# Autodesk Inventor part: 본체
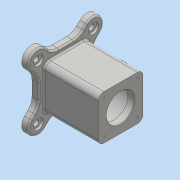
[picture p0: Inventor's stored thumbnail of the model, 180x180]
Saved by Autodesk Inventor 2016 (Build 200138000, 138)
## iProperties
Created: 2019-11
Part Number: 본체
Material: 일반
Document SubType Name: Modeling
Designer: user
Density: 1 g/cm^3
Appearance: 기본값
Author: user
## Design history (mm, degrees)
sketch "스케치1"
  geometry: L1 (-49, -49)-(49, -49); L2 (49, -49)-(49, 49); L3 (49, 49)-(-49, 49); L4 (-49, 49)-(-49, -49); L5 (-49, -49)-(49, 49); L6 (49, -49)-(-49, 49); L7 (49.497, -49.497)-(-49.497, 49.497); L8 (62.225, -36.77)-(-36.77, 62.225); L9 (-62.225, 36.77)-(36.77, -62.225); L10 (49.497, 49.497)-(-49.497, -49.497); L11 (36.77, 62.225)-(-62.225, -36.77); L12 (-36.77, -62.225)-(62.225, 36.77); A1 r 18 centre (49.497, -49.497) between (36.77, -62.225) and (62.225, -36.77); A2 r 18 centre (-49.497, 49.497) between (-36.77, 62.225) and (-62.225, 36.77); A3 r 18 centre (49.497, 49.497) between (62.225, 36.77) and (36.77, 62.225); A4 r 18 centre (-49.497, -49.497) between (-62.225, -36.77) and (-36.77, -62.225); 1 further point
  constraints: 28 end point, 8 point on circle, 8 tangent, 4 centre point, 4 midpoint, 4 parallel, 2 point on line, 1 horizontal, 1 perpendicular
  dimensions: "d72" = 98 distance of L3.end L2.end; "d73" = 98 distance of L2.end L1.end; "d74" = 18 radius of A2; "d75" = 18 radius of A4; "d76" = 140 distance of L10.start L10.end; "d77" = 140 distance of L7.start L7.end
extrude "돌출1" new body sketch "스케치1" distance "d7" = 12; taper "d8" = 0 deg
sketch "스케치2"
  geometry: L1 (-40, -40)-(40, -40); L2 (40, -40)-(40, 40); L3 (40, 40)-(-40, 40); L4 (-40, 40)-(-40, -40); L5 (-40, -40)-(40, 40); L6 (40, -40)-(-40, 40); 1 further point
  constraints: 12 end point, 2 midpoint, 2 parallel, 1 horizontal, 1 perpendicular
  dimensions: "d9" = 80 distance of L3.end L2.end; "d10" = 80 distance of L2.end L1.end
extrude "돌출2" join sketch "스케치2" distance "d11" = 98; taper "d12" = 0 deg
sketch "스케치3"
  geometry: C1 r 9 at (49.497, -49.497); A1 r 18 centre (49.497, -49.497) between (36.77, -62.225) and (62.225, -36.77) reference; 1 further point
  constraints: 1 centre point, 1 concentric
  dimensions: "d13" = 18 diameter of C1
extrude "돌출3" cut sketch "스케치3" distance "d14" = 4; taper "d15" = 0 deg
sketch "스케치4"
  geometry: C1 r 5 at (0, 0); C2 r 9 at (0, 0) reference; 1 further point
  constraints: 1 centre point, 1 concentric
  dimensions: "d16" = 10 diameter of C1
extrude "돌출4" cut sketch "스케치4" distance "d17" = 38.25; taper "d18" = 0 deg
sketch "스케치5"
  geometry: L1 (-12, 63.544)-(-12, 16.456) reference; C1 r 20 at (49, 40); 1 further point
  constraints: 1 centre point, 1 horizontal alignment, 1 midpoint
  dimensions: "d25" = 40 diameter of C1; "d78" = 61 distance from line of L1 C1.centre
extrude "돌출5" join sketch "스케치5" distance "d27" = 15; taper "d28" = 0 deg
sketch "스케치6"
  geometry: C1 r 15 at (0, 0); C2 r 20 at (0, 0) reference; 1 further point
  constraints: 1 centre point, 1 concentric
  dimensions: "d29" = 30 diameter of C1
extrude "돌출6" cut sketch "스케치6" distance "d30" = 8; taper "d31" = 0 deg
sketch "스케치7"
  geometry: C1 r 12.5 at (0, 0); C2 r 15 at (0, 0) reference; 1 further point
  constraints: 1 centre point, 1 concentric
  dimensions: "d32" = 25 diameter of C1
extrude "돌출7" cut sketch "스케치7" distance "d33" = 27.5; taper "d34" = 0 deg
sketch "스케치8"
  geometry: C1 r 25 at (0, 0); 1 further point
  constraints: 1 centre point, 1 coincident
  dimensions: "d35" = 50 diameter of C1
extrude "돌출8" cut sketch "스케치8" distance "d36" = 12; taper "d37" = 0 deg
sketch "스케치9"
  geometry: C1 r 35 at (0, 0); 1 further point
  constraints: 1 centre point, 1 coincident
  dimensions: "d38" = 70 diameter of C1
extrude "돌출9" cut sketch "스케치9" distance "d39" = 86; taper "d40" = 0 deg
sketch "스케치10"
  geometry: C1 r 25 at (0, 0) reference; C2 r 25 at (0, 0); 1 further point
  constraints: 1 centre point, 1 coincident
  dimensions: "d41" = 50 diameter of C2
extrude "돌출10" cut sketch "스케치10" distance "d42" = 12; taper "d43" = 0 deg
sketch "스케치11"
  geometry: L1 (30, 30)-(-30, 30); L2 (-30, 30)-(-30, -30); L3 (-30, -30)-(30, -30); L4 (30, -30)-(30, 30); L5 (30, 30)-(-30, -30); L6 (-30, 30)-(30, -30); 2 further points
  constraints: 12 end point, 2 midpoint, 2 parallel, 1 coincident, 1 horizontal, 1 perpendicular
  dimensions: "d44" = 60 distance of L3.end L2.end; "d45" = 60 distance of L2.end L1.end
hole "구멍1" sketch "스케치11" at (30, -30) diameter "d46" = 3.242; stored, may be unused: countersink angle "d50" = 90 deg, drill point angle "d52" = 118 deg; dims "d47" = 8, "d48" = 4, "d49" = 2, "d51" = 10
node "작업 평면1"
fillet "모깎기1" dims "d59" = 25
fillet "모깎기2" dims "d60" = 3
fillet "모깎기3" dims "d61" = 3
fillet "모깎기4" dims "d62" = 10
chamfer "모따기1" distance "d63" = 1; stored, may be unused: second distance "d64" = 2, angle "d65" = 45 deg
sketch "스케치12"
  geometry: L1 (98, 60)-(98, 0) reference; 2 further points
  constraints: 1 horizontal alignment, 1 midpoint, 1 other
  dimensions: "d66" = 10 distance from line of L1 point (88, 30)
feature "엠보싱1" sketch "스케치12" dims "d67" = 0.5, "d68" = 0
chamfer "모따기2" distance "d69" = 1; stored, may be unused: second distance "d70" = 2, angle "d71" = 45 deg
fillet "모깎기5" dims "d82" = 3
node "솔리드1"
pattern_linear "직사각형 패턴2" dims "d55" = 60
mirror "대칭1"
pattern_circular "원형 패턴1" dims angle "d80" = 360 deg
